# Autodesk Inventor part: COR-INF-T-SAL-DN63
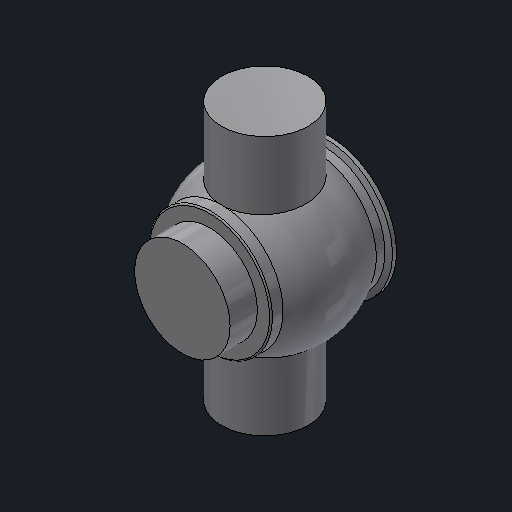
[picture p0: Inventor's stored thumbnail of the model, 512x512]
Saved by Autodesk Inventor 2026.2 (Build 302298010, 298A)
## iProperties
Created: 2026-03
Part Number: COR-INF-T-SAL-DN63
Material: Generico
Document SubType Name: Modeling
Designer: marz-m
Density: 1 g/cm^3
Appearance: Default
Author: marz-m
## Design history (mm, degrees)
feature "Solido1"
node "Solido2"
